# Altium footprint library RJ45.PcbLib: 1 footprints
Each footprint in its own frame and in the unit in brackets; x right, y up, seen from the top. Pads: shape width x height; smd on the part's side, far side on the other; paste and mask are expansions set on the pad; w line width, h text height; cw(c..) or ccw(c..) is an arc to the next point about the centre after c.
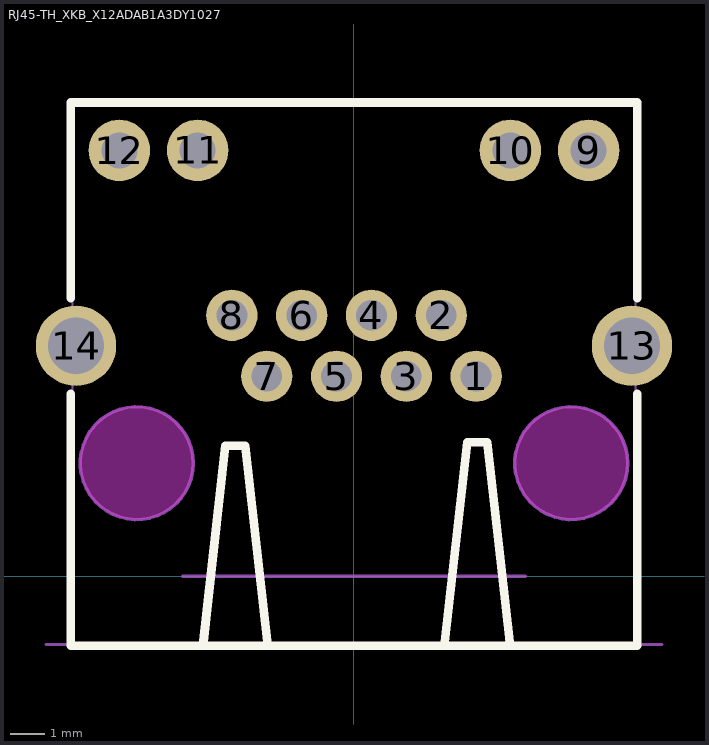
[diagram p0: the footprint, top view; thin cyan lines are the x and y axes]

## RJ45-TH_XKB_X12ADAB1A3DY1027 [mm]
pads (14):
  round 1.5 hole 0.9: 1(3.57,5.84) 2(2.55,7.62) 3(1.53,5.84) 4(0.51,7.62) 5(-0.51,5.84) 7(-2.55,5.84) 8(-3.57,7.62)
  round 1.5 hole 0.9 copper offset 0,0: 6(-1.53,7.62)
  round 1.8 hole 1.05: 9(6.86,12.44) 10(4.57,12.44) 11(-4.57,12.44) 12(-6.86,12.44)
  round 2.35 hole 1.65: 13(8.125,6.73) 14(-8.125,6.73)
Top Overlay:
  lines w0.254: -8.275,-2.033 -8.275,5.332 ; -8.275,8.128 -8.275,13.842 8.275,13.842 8.275,8.128 ; -8.255,-2.033 8.275,-2.033 8.275,5.332 ; -4.414,-2.033 -3.758,3.809 -3.175,3.809 -2.519,-2.033 ; 2.652,-1.928 3.308,3.914 3.892,3.914 4.547,-1.928
Keep-Out Layer:
  board cut-out: -4.7,3.3 -4.701,3.462 -4.765,3.78 -4.89,4.079 -5.071,4.348 -5.3,4.577 -5.57,4.757 -5.87,4.88 -6.188,4.944 -6.512,4.944 -6.83,4.88 -7.13,4.757 -7.4,4.577 -7.629,4.348 -7.81,4.079 -7.935,3.78 -7.999,3.462 -8,3.3 -7.999,3.138 -7.935,2.82 -7.81,2.521 -7.629,2.252 -7.4,2.023 -7.13,1.843 -6.83,1.72 -6.512,1.656 -6.188,1.656 -5.87,1.72 -5.57,1.843 -5.3,2.023 -5.071,2.252 -4.89,2.521 -4.765,2.82 -4.701,3.138 -4.7,3.3
  board cut-out: 8,3.3 7.999,3.462 7.935,3.78 7.81,4.079 7.629,4.348 7.4,4.577 7.13,4.757 6.83,4.88 6.512,4.944 6.188,4.944 5.87,4.88 5.57,4.757 5.3,4.577 5.071,4.348 4.89,4.079 4.765,3.78 4.701,3.462 4.7,3.3 4.701,3.138 4.765,2.82 4.89,2.521 5.071,2.252 5.3,2.023 5.57,1.843 5.87,1.72 6.188,1.656 6.512,1.656 6.83,1.72 7.13,1.843 7.4,2.023 7.629,2.252 7.81,2.521 7.935,2.82 7.999,3.138 8,3.3
Mechanical 1:
  circle w0.1: c6.35,3.3 r1.65
  circle w0.1: c-6.35,3.3 r1.65
  circle w0.1: c-6.35,3.3 r1.65
  circle w0.1: c6.35,3.3 r1.65
  lines w0.1: -5,0 5,0
Mechanical 15:
  drawing of 20 lines, arcs and shapes, not listed
3D body "RJ45-TH_XKB_X12ADAB1A3DY1027.step": height 13.1, standoff -3.45, extent -8.325,-1.995 8.325,13.855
